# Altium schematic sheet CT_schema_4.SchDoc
size 145 x 108 mm
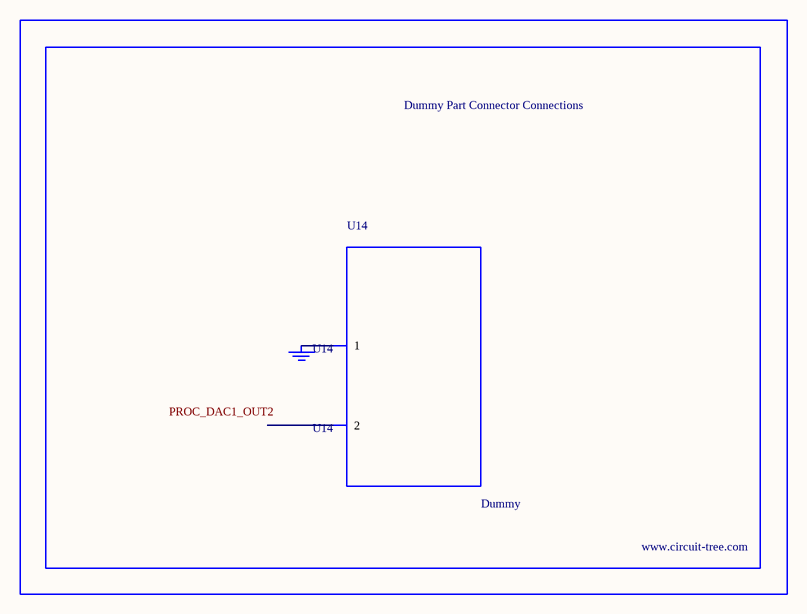
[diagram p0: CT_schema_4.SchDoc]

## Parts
BORDER3  (no value)
GND_INSTANCE_3_0  (no value)
U14  Dummy  [DUMMY_PACKAGE_119]

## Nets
NetGND_INSTANCE_3_0_0: GND_INSTANCE_3_0.0(GND) U14.1

Not connected (* = marked no-connect by the designer): U14 2

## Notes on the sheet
- Labels drawn without touching a wire or pin: PROC_DAC1_OUT2

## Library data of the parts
BORDER3 = BORDER_PAGE3
GND_INSTANCE_3_0 = GND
